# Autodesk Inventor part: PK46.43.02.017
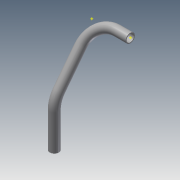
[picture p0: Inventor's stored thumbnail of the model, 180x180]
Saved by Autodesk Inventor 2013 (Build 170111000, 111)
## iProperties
Shininess: 64.0
Length Units: 11269
Angle Units: 11279
Time Units: 11290
Mass Units: 11283
Length Display Precision: 3
Angle Display Precision: 2
Compacted: True
Part Number: PK46.43.02.017
Document SubType Name: Modeling
Created: 2004-12
Material: Steel, High Strength Low Alloy
Designer: ELarisa
Manufacturer: Standard
Standards Organization: Custom
Density: 7.84 g/cm^3
Density: 0.0
Volumn: 0.0
Area: 0.0
PropertySet Name: Model Information
Control State: 0
Master: False
Checked Out: False
Checked Out Date: 2008-10-09
Last Check In Date: 2008-10-09
Author: ELarisa
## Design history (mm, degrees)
node "РабПлоскость1"
sketch "Эскиз5"
  geometry: C1 r 13 at (0, 0); C2 r 16 at (0, 0)
  constraints: 2 centre point, 1 coincident
  dimensions: "d12" = 32 diameter of C2; "d13" = 26 diameter of C1
sketch "Эскиз6"
  geometry: L1 (16, 0)-(-16, 0) reference; 3 further points
  dimensions: "d14" = 150 distance of point (0, 150) point (0, 0); "d15" = 330 vertical distance of point (130, 330) point (0, 0); "d16" = 130 horizontal distance of point (130, 330) point (0, 0)
node "РабТочка4"
node "РабТочка5"
node "РабТочка7"
node "РабТочка8"
sketch "3М эскиз3" dims "d25" = 80 (= d24)
  geometry: L1 through (80, 122.551) direction (-1, 0); 8 other entities
  constraints: 2 horizontal
  dimensions: "d24" = 80 dimension on L1
feature "Сдвиг3" sketch "3М эскиз3" dims "d26" = 0
body "Solid1"
sketch "Эскиз7"
  geometry: 2 further points
  dimensions: "d22" = 125 distance of point (-125, 330) point (0, 330); "d23" = 0 vertical distance of point (-125, 330) point (0, 330)
